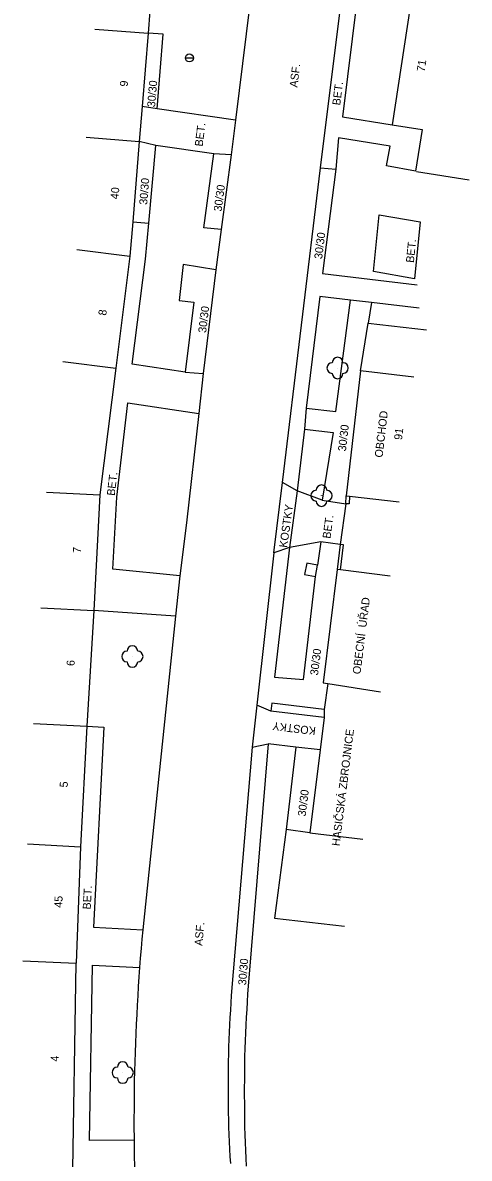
# Model space of a CAD drawing. Extents: x -544674 to -541478, y -1199076 to -1195527.
# Drawn here: x -543865.9 to -543824.1, y -1197284.1 to -1197177.8 of the extents above; entities that cross this region are included whole.
import ezdxf

# ---------------------------------------------------------------- set-up
doc = ezdxf.new("R2010")
doc.units = 0
for name, color, linetype in [('BUDOVY_MĚŘ', 7, 'Continuous'), ('POMOC_POPIS', 7, 'Continuous'), ('ROZHRANÍ_PLOCH', 7, 'Continuous'), ('ZELEŇ', 7, 'Continuous'), ('ZN_DOPLŇKOVÉ', 7, 'Continuous'), ('Č_POPIS_ORIENT', 7, 'Continuous')]:
    doc.layers.add(name, color=color, linetype=linetype)

msp = doc.modelspace()

# ---------------------------------------------------------------- linework, layer by layer
at = {"layer": 'BUDOVY_MĚŘ'}
for points in [[(-543853.83, -1197174.57), (-543854.14, -1197178.74)], [(-543829.58, -1197176.27), (-543831.28, -1197187.32)], [(-543859.13, -1197178.37), (-543854.14, -1197178.74)], [(-543854.14, -1197178.74), (-543854.71, -1197185.61)], [(-543854.71, -1197185.61), (-543854.98, -1197188.88)], [(-543831.28, -1197187.32), (-543828.48, -1197187.75), (-543829.08, -1197191.65)], [(-543859.96, -1197188.47), (-543854.98, -1197188.88)], [(-543854.98, -1197188.88), (-543855.59, -1197196.39)], [(-543824.05, -1197192.49), (-543829, -1197191.73)], [(-543855.59, -1197196.39), (-543855.86, -1197199.63)], [(-543860.82, -1197199), (-543855.86, -1197199.63)], [(-543855.86, -1197199.63), (-543857.18, -1197210.1)], [(-543862.14, -1197209.48), (-543857.18, -1197210.1)], [(-543857.18, -1197210.1), (-543858.67, -1197221.98)], [(-543834.23, -1197210.38), (-543835.58, -1197222.08)], [(-543829.26, -1197210.95), (-543834.23, -1197210.38)], [(-543863.66, -1197221.73), (-543858.67, -1197221.98)], [(-543858.67, -1197221.98), (-543859.22, -1197232.81)], [(-543835.58, -1197222.08), (-543835.28, -1197222.11)], [(-543835.28, -1197222.11), (-543830.61, -1197222.65)], [(-543836.43, -1197228.98), (-543837.75, -1197239.58), (-543837.31, -1197239.65)], [(-543836.13, -1197229.02), (-543836.43, -1197228.98)], [(-543831.47, -1197229.6), (-543836.13, -1197229.02)], [(-543864.21, -1197232.56), (-543859.22, -1197232.81)], [(-543859.22, -1197232.81), (-543859.89, -1197243.67)], [(-543837.31, -1197239.65), (-543837.65, -1197242.09)], [(-543837.31, -1197239.65), (-543832.37, -1197240.44)], [(-543837.66, -1197242.84), (-543838.03, -1197245.88)], [(-543837.65, -1197242.09), (-543837.66, -1197242.84)], [(-543864.88, -1197243.41), (-543859.89, -1197243.67)], [(-543859.89, -1197243.67), (-543860.47, -1197254.95)], [(-543838.03, -1197245.88), (-543838.99, -1197253.64)], [(-543838.99, -1197253.64), (-543834.03, -1197254.25)], [(-543865.46, -1197254.69), (-543860.47, -1197254.95)], [(-543860.47, -1197254.95), (-543860.9, -1197265.85)], [(-543865.9, -1197265.65), (-543860.9, -1197265.85)], [(-543861.23, -1197287.09), (-543860.9, -1197265.85)]]:
    msp.add_lwpolyline(points, dxfattribs=at)
at = {"layer": 'ROZHRANÍ_PLOCH'}
for points in [[(-543843.29, -1197165.37), (-543845.95, -1197186.87)], [(-543837.99, -1197191.35), (-543835.99, -1197175.28)], [(-543834.57, -1197175.46), (-543835.93, -1197186.58), (-543831.28, -1197187.32)], [(-543853.31, -1197185.81), (-543852.73, -1197178.82), (-543854.14, -1197178.74)], [(-543853.31, -1197185.81), (-543854.71, -1197185.61)], [(-543845.95, -1197186.87), (-543853.31, -1197185.81)], [(-543845.95, -1197186.87), (-543846.35, -1197190.13)], [(-543829.08, -1197191.65), (-543831.8, -1197191.17), (-543831.47, -1197189.31), (-543836.3, -1197188.54), (-543836.57, -1197191.48)], [(-543853.41, -1197189.25), (-543854.98, -1197188.88)], [(-543854.08, -1197196.53), (-543853.41, -1197189.25)], [(-543848, -1197190.03), (-543853.41, -1197189.25)], [(-543847.29, -1197197.13), (-543848.94, -1197196.98), (-543848, -1197190.03)], [(-543846.35, -1197190.13), (-543848, -1197190.03)], [(-543846.35, -1197190.13), (-543847.29, -1197197.13)], [(-543841.55, -1197220.82), (-543837.99, -1197191.35)], [(-543837.99, -1197191.35), (-543836.57, -1197191.48)], [(-543836.57, -1197191.48), (-543837.82, -1197201.24), (-543828.94, -1197202.31)], [(-543832.5, -1197195.74), (-543828.66, -1197196.41), (-543829.2, -1197201.73), (-543833.04, -1197201.06), (-543832.5, -1197195.74)], [(-543850.68, -1197210.48), (-543855.63, -1197209.75), (-543854.39, -1197199.89), (-543854.08, -1197196.53)], [(-543855.59, -1197196.39), (-543854.08, -1197196.53)], [(-543847.29, -1197197.13), (-543847.79, -1197200.9)], [(-543847.79, -1197200.9), (-543850.85, -1197200.41), (-543851.24, -1197203.78), (-543849.86, -1197203.92), (-543850.68, -1197210.48)], [(-543847.79, -1197200.9), (-543848.98, -1197210.62)], [(-543835.17, -1197203.73), (-543838.05, -1197203.39), (-543839.34, -1197213.85)], [(-543839.34, -1197213.85), (-543836.56, -1197214.19), (-543835.17, -1197203.73)], [(-543833.21, -1197203.96), (-543835.17, -1197203.73)], [(-543833.21, -1197203.96), (-543833.52, -1197205.9)], [(-543828.76, -1197204.48), (-543833.21, -1197203.96)], [(-543850.68, -1197210.48), (-543848.98, -1197210.62)], [(-543848.98, -1197210.62), (-543849.4, -1197214.35)], [(-543851.18, -1197229.58), (-543857.46, -1197228.96), (-543857.09, -1197222.19), (-543856.06, -1197213.37), (-543849.4, -1197214.35)], [(-543839.34, -1197213.85), (-543839.48, -1197215.82)], [(-543849.4, -1197214.35), (-543850.54, -1197224.61), (-543851.18, -1197229.58)], [(-543839.48, -1197215.82), (-543840.17, -1197221.6)], [(-543839.48, -1197215.82), (-543836.82, -1197216.15), (-543837.84, -1197222.48)], [(-543842.38, -1197227.43), (-543841.55, -1197220.82)], [(-543840.17, -1197221.6), (-543841.55, -1197220.82)], [(-543840.17, -1197221.6), (-543840.91, -1197226.92)], [(-543837.84, -1197222.48), (-543840.17, -1197221.6)], [(-543837.84, -1197222.48), (-543835.62, -1197222.82)], [(-543835.62, -1197222.82), (-543836.14, -1197226.63)], [(-543837.97, -1197226.38), (-543840.91, -1197226.92)], [(-543837.97, -1197226.38), (-543838.27, -1197228.58)], [(-543836.14, -1197226.63), (-543837.97, -1197226.38)], [(-543842.38, -1197227.43), (-543843.97, -1197241.68)], [(-543840.91, -1197226.92), (-543842.38, -1197227.43)], [(-543840.91, -1197226.92), (-543842.3, -1197239.06), (-543839.6, -1197239.29), (-543838.47, -1197229.64)], [(-543838.27, -1197228.58), (-543839.28, -1197228.38), (-543839.48, -1197229.44), (-543838.47, -1197229.64)], [(-543838.47, -1197229.64), (-543838.27, -1197228.58)], [(-543851.18, -1197229.58), (-543851.59, -1197233.35)], [(-543851.59, -1197233.35), (-543859.22, -1197232.81)], [(-543851.59, -1197233.35), (-543854.65, -1197262.73)], [(-543843.97, -1197241.68), (-543844.41, -1197245.62)], [(-543842.64, -1197242.25), (-543843.97, -1197241.68)], [(-543837.65, -1197242.09), (-543842.55, -1197241.5), (-543842.64, -1197242.25)], [(-543837.66, -1197242.84), (-543842.64, -1197242.25)], [(-543859.89, -1197243.67), (-543858.3, -1197243.75), (-543859.27, -1197262.5), (-543854.65, -1197262.73)], [(-543844.41, -1197245.62), (-543846.35, -1197268.9), (-543846.4, -1197269.58), (-543846.44, -1197270.27), (-543846.48, -1197270.95), (-543846.52, -1197271.63), (-543846.55, -1197272.32), (-543846.58, -1197273), (-543846.6, -1197273.69), (-543846.62, -1197274.37), (-543846.64, -1197275.06), (-543846.65, -1197275.74), (-543846.66, -1197276.43), (-543846.66, -1197277.11), (-543846.66, -1197277.8), (-543846.66, -1197278.48), (-543846.65, -1197279.16), (-543846.64, -1197279.85), (-543846.62, -1197280.53), (-543846.6, -1197281.22), (-543846.58, -1197281.9), (-543846.55, -1197282.59), (-543846.52, -1197283.27), (-543846.48, -1197283.96), (-543846.44, -1197284.64)], [(-543842.91, -1197245.3), (-543844.77, -1197268), (-543844.82, -1197268.73), (-543844.87, -1197269.47), (-543844.91, -1197270.2), (-543844.95, -1197270.93), (-543844.99, -1197271.66), (-543845.02, -1197272.4), (-543845.05, -1197273.13), (-543845.07, -1197273.86), (-543845.1, -1197274.6), (-543845.11, -1197275.33), (-543845.12, -1197276.07), (-543845.13, -1197276.8), (-543845.14, -1197277.53), (-543845.14, -1197278.27), (-543845.13, -1197279), (-543845.12, -1197279.74), (-543845.11, -1197280.47), (-543845.1, -1197281.2), (-543845.08, -1197281.94), (-543845.05, -1197282.67), (-543845.02, -1197283.4), (-543844.99, -1197284.14), (-543844.96, -1197284.87)], [(-543844.41, -1197245.62), (-543842.91, -1197245.3)], [(-543840.3, -1197245.61), (-543842.91, -1197245.3)], [(-543840.3, -1197245.61), (-543841.22, -1197253.34)], [(-543838.03, -1197245.88), (-543840.3, -1197245.61)], [(-543841.22, -1197253.34), (-543842.29, -1197261.65), (-543835.74, -1197262.4)], [(-543838.99, -1197253.64), (-543841.22, -1197253.34)], [(-543854.65, -1197262.73), (-543854.73, -1197263.61), (-543854.81, -1197264.5), (-543854.88, -1197265.38), (-543854.94, -1197266.26)], [(-543855.47, -1197282.44), (-543859.63, -1197282.46), (-543859.36, -1197266.04), (-543854.94, -1197266.26)], [(-543854.94, -1197266.26), (-543855.01, -1197267.14), (-543855.07, -1197268.03), (-543855.12, -1197268.91), (-543855.17, -1197269.8), (-543855.22, -1197270.68), (-543855.26, -1197271.57), (-543855.3, -1197272.45), (-543855.34, -1197273.33), (-543855.37, -1197274.22), (-543855.4, -1197275.11), (-543855.42, -1197275.99), (-543855.44, -1197276.88), (-543855.45, -1197277.76), (-543855.47, -1197278.65), (-543855.47, -1197279.53), (-543855.48, -1197280.42), (-543855.48, -1197281.3), (-543855.47, -1197282.19), (-543855.47, -1197282.44)], [(-543855.47, -1197282.44), (-543855.46, -1197283.08), (-543855.45, -1197283.96), (-543855.43, -1197284.85), (-543855.41, -1197285.73), (-543855.41, -1197285.82)]]:
    msp.add_lwpolyline(points, dxfattribs=at)
at = {"layer": 'ZELEŇ'}
for centre in [(-543836.39, -1197210.1), (-543837.9, -1197222.06), (-543855.62, -1197237.13), (-543856.53, -1197276.11)]:
    msp.add_circle(centre, 0.0005, dxfattribs=at)
for centre, start, end in [((-543836.89, -1197210.1), 89.99999, 269.99999), ((-543836.39, -1197209.6), 0, 179.99999), ((-543835.89, -1197210.1), 270, 89.99999), ((-543836.39, -1197210.6), 179.99999, 359.99999), ((-543838.4, -1197222.06), 89.99999, 269.99999), ((-543837.9, -1197221.56), 0, 179.99999), ((-543837.4, -1197222.06), 270, 89.99999), ((-543837.9, -1197222.56), 179.99999, 359.99999), ((-543855.62, -1197236.63), 0, 179.99999), ((-543856.12, -1197237.13), 89.99999, 269.99999), ((-543855.12, -1197237.13), 270, 89.99999), ((-543855.62, -1197237.63), 179.99999, 359.99999), ((-543857.03, -1197276.11), 89.99999, 269.99999), ((-543856.53, -1197275.61), 0, 179.99999), ((-543856.03, -1197276.11), 270, 89.99999), ((-543856.53, -1197276.61), 179.99999, 359.99999)]:
    msp.add_arc(centre, 0.5, start, end, dxfattribs=at)
at = {"layer": 'ZN_DOPLŇKOVÉ'}
msp.add_line((-543850.655, -1197181.05), (-543849.905, -1197181.05), dxfattribs=at)
for points in [[(-543834.23, -1197210.38), (-543833.52, -1197205.9)], [(-543833.52, -1197205.9), (-543828.07, -1197206.52)], [(-543835.62, -1197222.82), (-543835.58, -1197222.08)], [(-543835.28, -1197222.11), (-543835.32, -1197222.84), (-543835.62, -1197222.82)], [(-543836.14, -1197226.63), (-543836.43, -1197228.98)], [(-543836.13, -1197229.02), (-543835.84, -1197226.67), (-543836.14, -1197226.63)]]:
    msp.add_lwpolyline(points, dxfattribs=at)
msp.add_circle((-543850.28, -1197181.05), 0.375, dxfattribs=at)

# ---------------------------------------------------------------- texts
at = {"layer": 'POMOC_POPIS'}
for s, rotation, p in [('ASF.', 82.90997, (-543840.16, -1197183.85)), ('30/30', 85.26002, (-543853.5, -1197185.69)), ('BET.', 83.01001, (-543836.15, -1197185.52)), ('BET.', 82.99998, (-543849.04, -1197189.38)), ('30/30', 85.26002, (-543854.24, -1197194.83)), ('30/30', 82.35002, (-543847.27, -1197195.47)), ('30/30', 82.69998, (-543837.85, -1197199.93)), ('BET.', 84.19999, (-543829.25, -1197200.27)), ('30/30', 83.01998, (-543848.72, -1197206.84)), ('OBCHOD', 83.42002, (-543832.18, -1197218.52)), ('30/30', 83.42002, (-543835.62, -1197217.94)), ('BET.', 83.31001, (-543857.28, -1197222.1)), ('KOSTKY', 82.07999, (-543841.12, -1197226.97)), ('BET.', 82.22999, (-543837.07, -1197226.12)), ('OBECNÍ  ÚŘAD', 82.9, (-543834.25, -1197238.82)), ('30/30', 82.9, (-543838.23, -1197238.93)), ('KOSTKY', 173.19002, (-543838.4, -1197243.75)), ('HASIČSKÁ ZBROJNICE', 82.97999, (-543836.2, -1197254.92)), ('30/30', 82.97999, (-543839.39, -1197252.14)), ('BET.', 87.04002, (-543859.53, -1197260.84)), ('ASF.', 85.24002, (-543849.06, -1197264.26)), ('30/30', 85.32, (-543844.97, -1197267.95))]:
    msp.add_text(s, height=0.75, rotation=rotation, dxfattribs=at).set_placement(p)
at = {"layer": 'Č_POPIS_ORIENT'}
for s, rotation, p in [('71', 81.25, (-543828.24, -1197182.38)), ('9', 85.26002, (-543856.06, -1197183.76)), ('40', 85.32, (-543856.93, -1197194.31)), ('8', 82.80999, (-543858.08, -1197205.22)), ('91', 83.42002, (-543830.36, -1197216.87)), ('7', 87.08999, (-543860.45, -1197227.45)), ('6', 86.46999, (-543861.05, -1197238.04)), ('5', 87.06002, (-543861.69, -1197249.41)), ('45', 87.74001, (-543862.2, -1197260.68)), ('4', 89.11998, (-543862.54, -1197275.08))]:
    msp.add_text(s, height=0.75, rotation=rotation, dxfattribs=at).set_placement(p)

doc.saveas('drawing.dxf')
